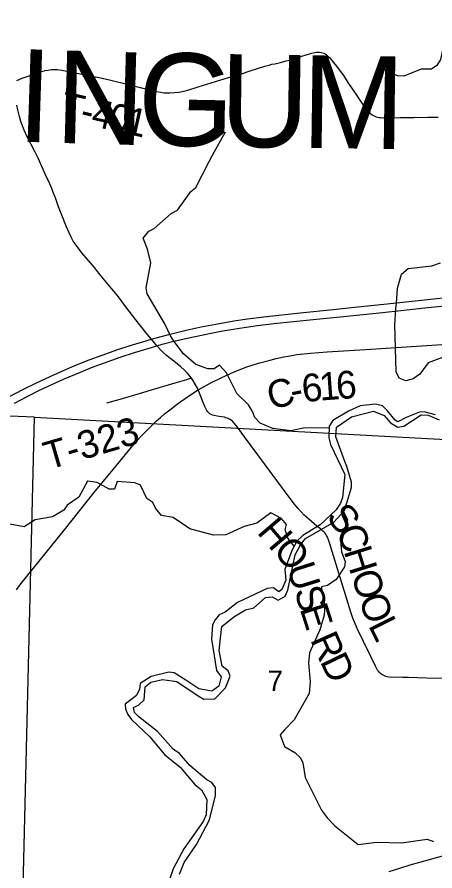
# Model space of a CAD drawing. Extents: x 0 to 34, y 0 to 22.
# Drawn here: x 2.935 to 3.791, y 14.491 to 16.238 of the extents above; entities that cross this region are included whole.
import ezdxf

# ---------------------------------------------------------------- set-up
doc = ezdxf.new("R2010")
doc.units = 0
for name, color, linetype in [('GM_X_Corporation', 7, 'Continuous'), ('GM_X_County_Road', 7, 'Continuous'), ('GM_X_County_Road_Text', 7, 'Continuous'), ('GM_X_County_Text', 7, 'Continuous'), ('GM_X_Minor_River', 7, 'Continuous'), ('GM_X_Rail_Line', 7, 'Continuous'), ('GM_X_Section_Text', 7, 'Continuous'), ('GM_X_State_Route', 7, 'Continuous'), ('GM_X_Township_Road', 7, 'Continuous'), ('GM_X_Township_Road_Text', 7, 'Continuous')]:
    doc.layers.add(name, color=color, linetype=linetype)

msp = doc.modelspace()

# ---------------------------------------------------------------- linework, layer by layer
at = {"layer": 'GM_X_Corporation'}
for points in [[(2.1, 15.4549), (2.1, 14.4331), (2.9463, 14.4019), (2.9706, 15.4194)], [(2.9706, 15.4194), (3.9769, 15.3648), (3.9619, 14.3814), (2.9463, 14.4019)]]:
    msp.add_lwpolyline(points, close=True, dxfattribs=at)
at = {"layer": 'GM_X_County_Road'}
for points in [[(3.3059, 15.4754), (3.3075, 15.4763), (3.3318, 15.49), (3.354, 15.501), (3.3796, 15.5123), (3.4056, 15.5223), (3.4292, 15.53), (3.4531, 15.5365), (3.4653, 15.5394), (3.4813, 15.5428), (3.4944, 15.5453), (3.5078, 15.5475), (3.5356, 15.5508), (3.5699, 15.5534), (3.6591, 15.5589), (3.8362, 15.5703), (3.8532, 15.5715), (3.8734, 15.573), (3.8993, 15.5755), (3.9215, 15.5778), (3.9414, 15.5802), (3.966, 15.5837), (3.9724, 15.5847)], [(2.9337, 15.0663), (2.9429, 15.0787), (3.0319, 15.1893), (3.0922, 15.2645), (3.1316, 15.3125), (3.163, 15.351), (3.179, 15.3698), (3.1897, 15.3812), (3.2011, 15.3932), (3.211, 15.4028), (3.2204, 15.4119), (3.2289, 15.4192), (3.2368, 15.4261), (3.2504, 15.4369), (3.2637, 15.4471), (3.2839, 15.4615), (3.3059, 15.4754)]]:
    msp.add_lwpolyline(points, dxfattribs=at)
at = {"layer": 'GM_X_Minor_River'}
for points in [[(3.9737, 16.3586), (3.9672, 16.3431), (3.9366, 16.3195), (3.9114, 16.2986), (3.8574, 16.265), (3.8355, 16.2459), (3.8242, 16.2334), (3.8078, 16.1772), (3.8019, 16.1514), (3.7947, 16.1392), (3.7838, 16.1316), (3.7626, 16.1315), (3.7271, 16.1173), (3.7142, 16.1177), (3.6823, 16.1327)], [(3.5741, 15.3975), (3.5205, 15.3973), (3.4955, 15.3919), (3.4588, 15.3967), (3.4326, 15.4072), (3.4216, 15.4186), (3.4174, 15.4311), (3.409, 15.4447), (3.3847, 15.4678), (3.364, 15.5105), (3.3492, 15.5257), (3.3386, 15.5184), (3.3258, 15.5188), (3.3011, 15.5274), (3.2761, 15.5489), (3.257, 15.5743), (3.249, 15.586), (3.2376, 15.6106), (3.2013, 15.6716), (3.1994, 15.6841), (3.2086, 15.7353), (3.2021, 15.7634), (3.1933, 15.7857), (3.2046, 15.8002), (3.2155, 15.8059), (3.2502, 15.8364), (3.2634, 15.8433), (3.2905, 15.8813), (3.3011, 15.8893), (3.3285, 15.9425), (3.3352, 15.9558), (3.3619, 16.0037)], [(3.8094, 15.5429), (3.7769, 15.531), (3.7671, 15.5181), (3.7596, 15.5074), (3.746, 15.4983), (3.7313, 15.4941), (3.7176, 15.4993), (3.7115, 15.5122), (3.7084, 15.6085), (3.7109, 15.6412), (3.712, 15.6526), (3.7138, 15.6837), (3.7224, 15.7122), (3.7356, 15.7236), (3.784, 15.7291), (3.8021, 15.7356)], [(3.7917, 15.4245), (3.7686, 15.4308), (3.7588, 15.43), (3.7316, 15.4189), (3.7147, 15.4099), (3.709, 15.4137), (3.6937, 15.4325), (3.683, 15.4427), (3.669, 15.4464), (3.6376, 15.4425), (3.6138, 15.4318)], [(3.6138, 15.4318), (3.5817, 15.4131), (3.5742, 15.4009), (3.5732, 15.3774), (3.5766, 15.3634), (3.6064, 15.302), (3.6017, 15.2553), (3.5976, 15.2436), (3.5882, 15.2299), (3.5557, 15.1994), (3.5203, 15.1776), (3.5082, 15.1662), (3.4973, 15.1468), (3.4835, 15.1077), (3.4851, 15.0861), (3.4773, 15.067), (3.4712, 15.0621), (3.4602, 15.0701), (3.4473, 15.0689), (3.3865, 15.0402), (3.3609, 15.0207), (3.3491, 15.0154), (3.3405, 15.0051), (3.3352, 14.9949), (3.3331, 14.9656), (3.3432, 14.9016), (3.3527, 14.8883), (3.3483, 14.8693), (3.3339, 14.8587), (3.3074, 14.8635), (3.2805, 14.8812), (3.2565, 14.8963), (3.2456, 14.8982), (3.2093, 14.8893), (3.187, 14.8748), (3.1859, 14.8631), (3.1795, 14.8501), (3.1565, 14.8322), (3.1569, 14.822), (3.1619, 14.8114), (3.1691, 14.8008), (3.2068, 14.7656), (3.2368, 14.7293), (3.2687, 14.7036), (3.2988, 14.6684), (3.3125, 14.6571), (3.3235, 14.6374), (3.3221, 14.6063), (3.3158, 14.5923), (3.2763, 14.5367), (3.2549, 14.4957), (3.2448, 14.4676)], [(3.2674, 14.4843), (3.2768, 14.5083), (3.3027, 14.5452), (3.329, 14.5961), (3.3413, 14.6458), (3.3412, 14.6618), (3.3336, 14.672), (3.3234, 14.6773), (3.2888, 14.7067), (3.2679, 14.7317), (3.2546, 14.7404), (3.2226, 14.7763), (3.185, 14.8058), (3.1751, 14.8156), (3.1736, 14.8254), (3.1842, 14.8308), (3.1951, 14.8415), (3.1972, 14.8676), (3.2086, 14.8775), (3.2331, 14.8826), (3.2623, 14.8789), (3.306, 14.8494), (3.3173, 14.8427), (3.34, 14.8431), (3.3619, 14.8656), (3.3716, 14.8895), (3.3671, 14.9005), (3.3553, 14.9103), (3.3491, 14.9422), (3.3531, 14.9794), (3.3545, 14.9911), (3.3791, 15.0113), (3.4029, 15.0255), (3.4195, 15.0293), (3.444, 15.0506), (3.4572, 15.0522), (3.4698, 15.045), (3.4841, 15.0531), (3.4897, 15.0656), (3.5045, 15.1376), (3.5151, 15.1583), (3.5257, 15.1712), (3.5838, 15.2048), (3.6052, 15.2284), (3.6198, 15.2755), (3.6197, 15.2869), (3.6105, 15.3187), (3.6063, 15.3289), (3.5875, 15.3797), (3.5894, 15.3991), (3.6195, 15.4204), (3.6649, 15.4316), (3.6865, 15.4233), (3.6998, 15.4082), (3.7146, 15.3988)], [(3.2674, 14.4843), (3.2768, 14.5083), (3.3027, 14.5452), (3.329, 14.5961), (3.3413, 14.6458), (3.3412, 14.6618), (3.3336, 14.672), (3.3234, 14.6773), (3.2888, 14.7067), (3.2679, 14.7317), (3.2546, 14.7404), (3.2226, 14.7763), (3.185, 14.8058), (3.1751, 14.8156), (3.1736, 14.8254), (3.1842, 14.8308), (3.1951, 14.8415), (3.1972, 14.8676), (3.2086, 14.8775), (3.2331, 14.8826), (3.2623, 14.8789), (3.306, 14.8494), (3.3173, 14.8427), (3.34, 14.8431), (3.3619, 14.8656), (3.3716, 14.8895), (3.3671, 14.9005), (3.3553, 14.9103), (3.3491, 14.9422), (3.3531, 14.9794), (3.3545, 14.9911), (3.3791, 15.0113), (3.4029, 15.0255), (3.4195, 15.0293), (3.444, 15.0506), (3.4572, 15.0522), (3.4698, 15.045), (3.4841, 15.0531), (3.4897, 15.0656), (3.5045, 15.1376), (3.5151, 15.1583), (3.5257, 15.1712), (3.5838, 15.2048), (3.6052, 15.2284), (3.6198, 15.2755), (3.6197, 15.2869), (3.6105, 15.3187), (3.6063, 15.3289), (3.5875, 15.3797), (3.5894, 15.3991), (3.6195, 15.4204), (3.6649, 15.4316), (3.6865, 15.4233), (3.6998, 15.4082), (3.7146, 15.3988)], [(3.7146, 15.3988), (3.7271, 15.4011), (3.7622, 15.4244), (3.7766, 15.4237), (3.7994, 15.4143)], [(3.5025, 15.156), (3.4893, 15.1718), (3.4843, 15.1893), (3.4869, 15.1999), (3.4766, 15.212), (3.4546, 15.2237), (3.4259, 15.2027), (3.4002, 15.1962), (3.3628, 15.1786), (3.3375, 15.1781), (3.2886, 15.1912), (3.2548, 15.2146), (3.2309, 15.2187), (3.2184, 15.2331), (3.213, 15.2452), (3.2009, 15.2535), (3.1948, 15.266), (3.1879, 15.2804), (3.1758, 15.2853), (3.1402, 15.2882), (3.1342, 15.2726), (3.1236, 15.2722), (3.0993, 15.2861), (3.0792, 15.2887), (3.0612, 15.256), (3.0374, 15.2396), (3.0306, 15.229), (3.0076, 15.2156), (2.972, 15.2098), (2.9498, 15.1949), (2.9089, 15.2028)], [(3.6033, 15.2263), (3.6117, 15.2097), (3.5979, 15.1588), (3.5991, 15.1441), (3.6067, 15.1244), (3.6057, 15.1134), (3.5883, 15.0875), (3.571, 15.0753), (3.5581, 15.0722), (3.5589, 15.0623), (3.5655, 15.035), (3.564, 15.0145), (3.5551, 14.9845), (3.5341, 14.9374), (3.5319, 14.9161), (3.5351, 14.8778), (3.5333, 14.8539), (3.5025, 14.8007), (3.4829, 14.7801), (3.4738, 14.7694), (3.4823, 14.7456), (3.504, 14.7335), (3.5154, 14.7226), (3.5203, 14.7127), (3.525, 14.6824), (3.5587, 14.6158), (3.5709, 14.5992), (3.5857, 14.5837), (3.6337, 14.5452), (3.6708, 14.5503), (3.722, 14.5486), (3.7746, 14.5565), (3.7875, 14.5516)]]:
    msp.add_lwpolyline(points, dxfattribs=at)
at = {"layer": 'GM_X_Rail_Line'}
msp.add_lwpolyline([(3.6972, 14.4902), (3.7191, 14.4967), (3.74, 14.5034), (3.7793, 14.5148), (3.8138, 14.5243), (3.839, 14.5311), (3.862, 14.5367), (3.9255, 14.5525), (3.9926, 14.5684), (4.075, 14.5889), (4.2057, 14.6209), (4.3124, 14.6473), (4.4566, 14.6827), (4.5938, 14.7167), (4.7232, 14.7487), (4.8596, 14.7823)], dxfattribs=at)
at = {"layer": 'GM_X_State_Route'}
for points in [[(2.9193, 15.4618), (2.9468, 15.4761), (2.9746, 15.4898), (3.0027, 15.503), (3.0311, 15.5156), (3.0568, 15.5264), (3.0828, 15.5368), (3.109, 15.5465), (3.1412, 15.5578), (3.1648, 15.5655), (3.2035, 15.5772), (3.2101, 15.5791), (3.2303, 15.5849), (3.2483, 15.5896), (3.2815, 15.5976), (3.3118, 15.6042), (3.3423, 15.6102), (3.379, 15.6165), (3.4066, 15.6206), (3.4405, 15.6249), (3.5146, 15.6332), (3.5825, 15.6402), (3.6258, 15.6447), (3.666, 15.6488), (3.7061, 15.653), (3.8327, 15.6663)], [(2.9296, 15.4485), (2.9571, 15.4629), (2.9821, 15.4754), (3.0046, 15.486), (3.0302, 15.4973), (3.0646, 15.5117), (3.0876, 15.5209), (3.1138, 15.5307), (3.1461, 15.5421), (3.1756, 15.5519), (3.2053, 15.5611), (3.2213, 15.5658), (3.2321, 15.5689), (3.2562, 15.5752), (3.2835, 15.5814), (3.3321, 15.5916), (3.3565, 15.5962), (3.3903, 15.6017), (3.4272, 15.6069), (3.4611, 15.611), (3.5415, 15.6193), (3.6032, 15.6258), (3.6434, 15.6299), (3.6836, 15.634), (3.7207, 15.6378), (3.7762, 15.6437), (3.8441, 15.6511)]]:
    msp.add_lwpolyline(points, dxfattribs=at)
at = {"layer": 'GM_X_Township_Road'}
for points in [[(2.9342, 16.1084), (2.9455, 16.1132), (2.9662, 16.1203), (2.9839, 16.1261), (2.9928, 16.1286), (2.9989, 16.1298), (3.0051, 16.1306), (3.0113, 16.1308), (3.0175, 16.1306), (3.0267, 16.1294), (3.0542, 16.1243), (3.0846, 16.1182), (3.109, 16.1134), (3.1271, 16.1093), (3.1603, 16.1012), (3.1873, 16.094), (3.2053, 16.0893), (3.2204, 16.0858), (3.2296, 16.0842), (3.2358, 16.0834), (3.2419, 16.083), (3.2481, 16.0829), (3.2574, 16.0835), (3.2666, 16.0848), (3.2758, 16.0866), (3.2848, 16.0889), (3.3056, 16.0952), (3.3501, 16.1088), (3.3679, 16.1143), (3.3947, 16.1223), (3.4124, 16.1279), (3.4272, 16.1326), (3.442, 16.1374), (3.4509, 16.1399), (3.4569, 16.1415), (3.4628, 16.1428), (3.4745, 16.1454), (3.4861, 16.1483), (3.4919, 16.1499), (3.5037, 16.1537), (3.5184, 16.1583), (3.5273, 16.161), (3.5388, 16.1644), (3.5449, 16.1657), (3.5484, 16.1662), (3.5511, 16.1664), (3.5545, 16.1663), (3.5574, 16.166), (3.5604, 16.1652), (3.5633, 16.1641), (3.566, 16.1627), (3.5686, 16.161), (3.571, 16.1591), (3.5753, 16.1547), (3.5833, 16.1452), (3.589, 16.1379), (3.5946, 16.1305), (3.6018, 16.1204), (3.614, 16.1024), (3.6259, 16.0843), (3.638, 16.0663), (3.6452, 16.0562), (3.6509, 16.0488), (3.655, 16.0443), (3.6572, 16.0421), (3.6595, 16.0402), (3.662, 16.0384), (3.6647, 16.0368), (3.6674, 16.0354), (3.6703, 16.0343), (3.6733, 16.0334), (3.6763, 16.0328), (3.6794, 16.0324), (3.6856, 16.0321), (3.6949, 16.032), (3.7197, 16.0324), (3.7476, 16.033), (3.7755, 16.0333), (3.7973, 16.0336)], [(3.292, 15.4995), (3.2897, 15.5027), (3.2837, 15.5098), (3.2773, 15.5166), (3.2703, 15.5227), (3.2558, 15.5344), (3.2413, 15.5461), (3.2319, 15.5542), (3.2213, 15.5658), (3.2101, 15.5791), (3.2016, 15.5894), (3.1785, 15.6186), (3.1576, 15.6456), (3.1446, 15.6631), (3.137, 15.6729), (3.1291, 15.6824), (3.119, 15.6942), (3.1053, 15.7109), (3.0976, 15.7205), (3.0958, 15.7229), (3.094, 15.7254), (3.0678, 15.7558), (3.0598, 15.766), (3.0557, 15.7717), (3.0501, 15.78), (3.0457, 15.7876), (3.0414, 15.7964), (3.0357, 15.8106), (3.0263, 15.8327), (3.0199, 15.8502), (3.0141, 15.8665), (3.0085, 15.8812), (3.0061, 15.8873), (3.0017, 15.8967), (2.9929, 15.9152), (2.9854, 15.9322), (2.978, 15.9492), (2.9714, 15.9632), (2.9557, 15.9934), (2.9497, 16.007), (2.9447, 16.0191), (2.9428, 16.0248), (2.9397, 16.0345), (2.9363, 16.0485), (2.9342, 16.0576)], [(3.1191, 15.449), (3.146, 15.4563), (3.1874, 15.4689), (3.2171, 15.4776), (3.2587, 15.4898), (3.2824, 15.4967), (3.2883, 15.4984), (3.292, 15.4995)], [(3.3059, 15.4754), (3.3043, 15.479), (3.3, 15.4872), (3.2951, 15.4951), (3.292, 15.4995)], [(3.8108, 14.8846), (3.7735, 14.8858), (3.7363, 14.8869), (3.724, 14.887), (3.6961, 14.8876), (3.6931, 14.8882), (3.6901, 14.8891), (3.6872, 14.8902), (3.6844, 14.8916), (3.6818, 14.8932), (3.6795, 14.8952), (3.6773, 14.8974), (3.6753, 14.8998), (3.6734, 14.9023), (3.6718, 14.9049), (3.6688, 14.9103), (3.6594, 14.9299), (3.6445, 14.9607), (3.6323, 14.9858), (3.626, 15), (3.6227, 15.0087), (3.6186, 15.0204), (3.6103, 15.047), (3.6048, 15.0648), (3.5857, 15.1271), (3.5747, 15.1627), (3.5727, 15.1686), (3.5705, 15.1743), (3.5688, 15.1778), (3.5673, 15.1802), (3.5649, 15.183), (3.563, 15.1849), (3.5609, 15.1866), (3.5563, 15.1908), (3.5491, 15.1967), (3.5324, 15.2107), (3.5232, 15.219), (3.5167, 15.2256), (3.5105, 15.2326), (3.5027, 15.2422), (3.4786, 15.2746), (3.4414, 15.3244), (3.4008, 15.3792), (3.3861, 15.3993), (3.3804, 15.4067), (3.3762, 15.4112), (3.3738, 15.4131), (3.3712, 15.4149), (3.3685, 15.4163), (3.3657, 15.4175), (3.3628, 15.4185), (3.3598, 15.4193), (3.3537, 15.4204), (3.3445, 15.4216), (3.3384, 15.4228), (3.3354, 15.4237), (3.3325, 15.4249), (3.3299, 15.4264), (3.3274, 15.4284), (3.3254, 15.4307), (3.3236, 15.4332), (3.3221, 15.436), (3.3195, 15.4416), (3.3149, 15.4531), (3.3081, 15.4705), (3.3059, 15.4754)]]:
    msp.add_lwpolyline(points, dxfattribs=at)

# ---------------------------------------------------------------- texts
at = {"layer": 'GM_X_County_Road_Text'}
for s, rotation, p in [('6', 4.0103, (3.59, 15.4561)), ('C', 13.6926, (3.4546, 15.4347)), ('6', 6.2465, (3.5209, 15.4498)), ('1', 4.1564, (3.5552, 15.4535)), ('-', 10.7649, (3.4992, 15.4456))]:
    msp.add_text(s, height=0.0568, rotation=rotation, dxfattribs=at).set_placement(p)
at = {"layer": 'GM_X_County_Text'}
for s, rotation, p in [('I', 358.1377, (2.9332, 15.9836)), ('N', 358.4214, (3.0116, 15.981)), ('G', 358.9475, (3.181, 15.9763)), ('U', 359.1434, (3.3492, 15.9733)), ('M', 359.1871, (3.5168, 15.9708))]:
    msp.add_text(s, height=0.1894, rotation=rotation, dxfattribs=at).set_placement(p)
at = {"layer": 'GM_X_Section_Text'}
msp.add_text('7', height=0.0419, rotation=0, dxfattribs=at).set_placement((3.4483, 14.8593))
at = {"layer": 'GM_X_Township_Road_Text'}
for s, height, rotation, p in [('T', 0.0568, 347.0719, (3.02, 16.0309)), ('4', 0.0568, 347.1127, (3.0842, 16.0162)), ('0', 0.0568, 347.2214, (3.1184, 16.0084)), ('-', 0.0568, 347.0752, (3.0614, 16.0214)), ('1', 0.0568, 347.5961, (3.1529, 16.0005)), ('T-323', 0.05682, 16.2706, (2.9992, 15.3117)), ('S', 0.0568, 309.2587, (3.5664, 15.2143)), ('H', 0.0568, 310.4231, (3.4246, 15.1835)), ('C', 0.0568, 289.4323, (3.5882, 15.1892)), ('O', 0.0568, 310.8319, (3.4573, 15.1451)), ('H', 0.0568, 287.3451, (3.6035, 15.1457)), ('U', 0.0568, 287.4131, (3.487, 15.1125)), ('O', 0.0568, 287.3503, (3.6184, 15.098)), ('S', 0.0568, 287.4123, (3.502, 15.0648)), ('O', 0.0568, 289.0194, (3.6339, 15.0485)), ('E', 0.0568, 287.6493, (3.5135, 15.028)), ('L', 0.0568, 296.515, (3.6533, 14.9938)), ('R', 0.0568, 294.1319, (3.5345, 14.9644)), ('D', 0.0568, 295.8621, (3.5543, 14.9201))]:
    msp.add_text(s, height=height, rotation=rotation, dxfattribs=at).set_placement(p)

doc.saveas('drawing.dxf')
